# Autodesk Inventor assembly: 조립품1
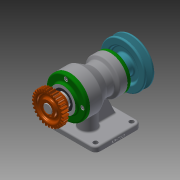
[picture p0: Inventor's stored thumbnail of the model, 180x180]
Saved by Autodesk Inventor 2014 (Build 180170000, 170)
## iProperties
Created: 2019-01
Part Number: 조립품1
Document SubType Name: Assembly
Designer: kh
Author: kh
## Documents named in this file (15)
- C:\Users\kh\Desktop\490107V1051\조립품1.iam
- C:\Users\kh\Desktop\490107V1051\본체.ipt
- C:\Users\kh\Desktop\490107V1051\V-벨트풀리.ipt
- C:\Users\kh\Desktop\490107V1051\뒤커버.ipt
- C:\Users\kh\Desktop\490107V1051\멈춤나사 M3.ipt
- C:\Users\kh\Desktop\490107V1051\베어링 6203.ipt
- C:\Users\kh\Desktop\490107V1051\베어링 6205.ipt
- C:\Users\kh\Desktop\490107V1051\볼트 M4.ipt
- C:\Users\kh\Desktop\490107V1051\스퍼기어.ipt
- C:\Users\kh\Desktop\490107V1051\앞커버.ipt
- C:\Users\kh\Desktop\490107V1051\오일 실 17 30 8.ipt
- C:\Users\kh\Desktop\490107V1051\오일 실 25 38 8.ipt
- C:\Users\kh\Desktop\490107V1051\축.ipt
- C:\Users\kh\Desktop\490107V1051\키 5 x 5 x 20.ipt
- C:\Users\kh\Desktop\490107V1051\키 6 x 6 x 18.ipt
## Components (1 placed, 1 different names)
1. V-벨트풀리:1
